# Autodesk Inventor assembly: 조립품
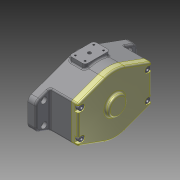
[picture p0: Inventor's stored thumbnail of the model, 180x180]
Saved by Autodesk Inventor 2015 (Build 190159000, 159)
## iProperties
Created: 2023-11
Part Number: 조립품
Document SubType Name: Assembly
Designer: user
Author: user
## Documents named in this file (14)
- C:\Users\user\Desktop\731106V1001\조립품.iam
- C:\Users\user\Desktop\731106V1001\본체.ipt
- C:\Users\user\Desktop\731106V1001\DU 부시.ipt
- C:\Users\user\Desktop\731106V1001\O링 G90.ipt
- C:\Users\user\Desktop\731106V1001\내접기어.ipt
- C:\Users\user\Desktop\731106V1001\스퍼기어.ipt
- C:\Users\user\Desktop\731106V1001\오일 실 14 25 4.ipt
- C:\Users\user\Desktop\731106V1001\오일레스 부시.ipt
- C:\Users\user\Desktop\731106V1001\축.ipt
- C:\Users\user\Desktop\731106V1001\커버.ipt
- C:\Users\user\Desktop\731106V1001\크레센트.ipt
- C:\Users\user\Desktop\731106V1001\평행 키 5x5x22.ipt
- C:\Users\user\Desktop\731106V1001\육각 소켓 머리 볼트 M6 x 12.ipt
- C:\Users\user\Desktop\731106V1001\육각 소켓 머리 볼트 M4 x 30.ipt
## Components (2 placed, 2 different names)
1. DU 부시:1
2. O링 G90:1
